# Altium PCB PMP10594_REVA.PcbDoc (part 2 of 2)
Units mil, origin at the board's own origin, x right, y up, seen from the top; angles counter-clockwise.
Board outline 4300 x 2600 mil, 4 copper layers (Top Layer, Signal Layer 1, Signal Layer 2, Bottom Layer), stack 61.2 mil thick; 149 components, 76 nets, 349 pads, 143 vias.
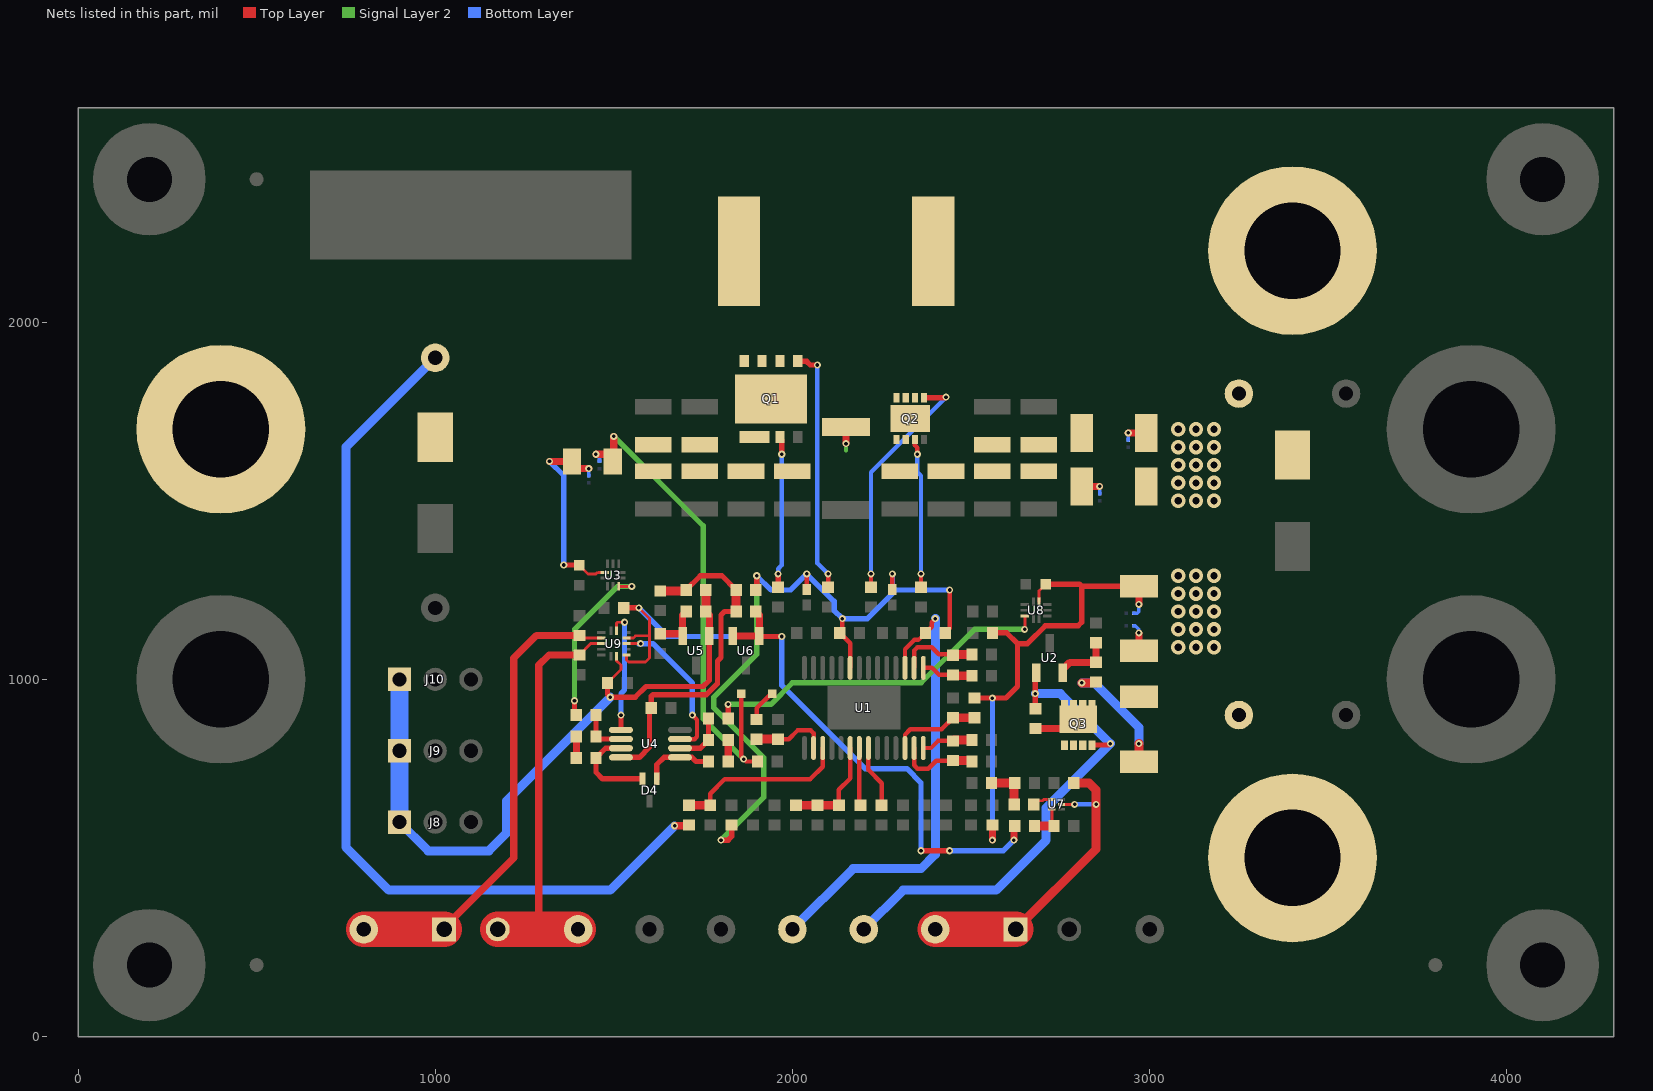
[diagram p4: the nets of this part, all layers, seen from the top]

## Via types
v1: diameter 20, hole 10, Top Layer to Bottom Layer, 105 vias
v2: diameter 40, hole 20, Top Layer to Bottom Layer, 38 vias

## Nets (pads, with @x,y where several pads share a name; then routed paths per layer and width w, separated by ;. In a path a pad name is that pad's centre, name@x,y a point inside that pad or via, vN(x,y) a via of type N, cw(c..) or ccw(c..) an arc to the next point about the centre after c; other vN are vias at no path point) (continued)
NetC15_1: C15.1 R15.1 U1.16 | length 220.9
  Top Layer w12.5: U1.16@2340.75,1032.2 2340.75,1080.75 2350,1090 2390,1090 2410,1070 2447.56,1070 C15.1@2450,1067.56
  Top Layer w25: C15.1@2452.44,1070 R15.1@2502.44,1070
NetC15_2: C15.2 R16.1 U1.15 | length 145.3
  Top Layer w12.5: U1.15@2366.34,1032.2 2390.55,1032.2 2410.31,1012.44 C15.2@2450,1012.44
  Top Layer w25: C15.2@2450,1012.44 2452.44,1010 R16.1@2502.44,1010
NetC16_1: C16.1 R17.2 | length 60
  Top Layer w20: R17.2@1395.04,780 C16.1@1395.04,840
NetC16_2: C16.2 R23.1 U4.6 | length 132.7
  Top Layer w15: R23.1@1450.16,900 C16.2@1450.16,840 1457.36,832.8 U4.6@1519.92,832.8
NetC18_1: C18.1 R18.2 U1.13 | length 220.9
  Top Layer w12.5: U1.13@2340.75,807.8 2340.75,759.25 2350,750 2380,750 2402.44,772.44 C18.1@2450,772.44
  Top Layer w25: C18.1@2450,772.44 R18.2@2500,772.44
NetC18_2: C18.2 R22.2 U1.14 | length 145.3
  Top Layer w12.5: U1.14@2366.34,807.8 2387.8,807.8 2407.56,827.56 C18.2@2450,827.56
  Top Layer w25: C18.2@2450,827.56 2452.44,830 R22.2@2502.44,830
NetC20_1: C20.1 R28.2 | length 60
  Top Layer w20: R28.2@1820.16,770 C20.1@1820.16,830
NetC20_2: C20.2 R33.1 U4.2 | length 149.2
  Top Layer w15: U4.2@1685.28,807.2 1742.24,807.2 C20.2@1765.04,830 R33.1@1765.04,890
NetC26_1: C26.1 R26.1 U7.6 | length 103.5
  Top Layer w7.87: C26.1@2726.48,595.83 U7.6@2726.48,636.22
  Top Layer w8: C26.1@2726.48,595.83 C26.1@2732.31,590
  Top Layer w25: R26.1@2677.43,590 C26.1@2732.31,590
NetD1_1: D1.1 R4.2 | length 92
  Top Layer w12.5: R4.2@1900,887.56 1900,919.5 1940.5,960 D1.1@1943.31,960
NetD4_1: D4.1 R28.1 U4.1 | length 198.1
  Top Layer w15: D4.1@1619.68,721.5 1619.68,760.79 1640.51,781.61 U4.1@1685.28,781.61 1718.39,781.61 1730,770 R28.1@1765.04,770
NetD4_2: D4.2 R17.1 U4.7 | length 258.9
  Top Layer w15: U4.7@1519.92,807.2 1477.36,807.2 R17.1@1450.16,780 1450.16,739.84 1468.5,721.5 D4.2@1580.31,721.5
NetL1_1: L1.1 Q1.6 Q1.7 Q1.8
NetL1_2: L1.2 Q2.6 Q2.7 Q2.8
NetNT5_1: NT5.1 Q1.9 Q2.9 RS4.2 | length 66.1
  Top Layer w20: v1(2150,1660) RS4.2@2150,1706.14
  Signal Layer 2 w10: NT5.1@2150,1640 v1(2150,1660)
NetNT8_2: NT8.2 Q3.5 Q3.6 Q3.7 Q3.8 Q3.9 R7.1 R9.1 RS5.2 | length 174.1
  Top Layer w20: R9.1@2680,862.44 Q3.9@2774.37,862.44 ; RS5.2@2970,1079.45 v1(2970,1130)
  Bottom Layer w10: NT8.2@2955,1150 2960,1150 2970,1140 v1(2970,1130)
NetQ1_3: Q1.3 RH1.2 | length 415.5
  Top Layer w15: RH1.2@1960,1257.56 v1(1960,1295) ; v1(1970,1630) Q1.3@1970,1668.9
  Bottom Layer w12.5: v1(1960,1295) 1960,1310 1970,1320 v1(1970,1630)
NetQ1_5: Q1.5 RL1.2 | length 694.5
  Top Layer w12.5: Q1.5@2015,1891.1 Q1.5@2016.1,1890 ; RL1.2@2100,1257.56 v1(2100,1295)
  Top Layer w15: Q1.5@2016.1,1890 2040,1890 2050,1880 v1(2070,1880)
  Bottom Layer w12.5: v1(2070,1880) 2070,1325 v1(2100,1295)
NetQ2_3: Q2.3 RH2.1 | length 421.3
  Top Layer w12.5: Q2.3@2342.8,1671.73 2342.8,1655.89 2350,1648.69 v1(2350,1630) ; RH2.1@2360,1257.56 v1(2360,1295)
  Bottom Layer w12.5: v1(2350,1630) 2350,1580 2360,1570 v1(2360,1295)
NetQ2_5: Q2.5 RL2.1 | length 681.8
  Top Layer w12.5: RL2.1@2220,1257.56 v1(2220,1295)
  Top Layer w15: Q2.5@2368.39,1788.27 2428.27,1788.27 v1(2430,1790)
  Bottom Layer w12.5: v1(2220,1295) 2220,1580 v1(2430,1790)
NetQ3_4: Q3.4 R9.2 TP8.1 U2.1 | length 1381.5
  Top Layer w15: R9.2@2680,917.56 v1(2680,960) 2680,1016.06 U2.1@2682.6,1018.66 ; Q3.4@2838.39,816.02 2886.02,816.02 v1(2890,820)
  Bottom Layer w25: TP8.1@2200,300 2310,410 2570,410 2710,550 2710,640 v1(2890,820) 2750,960 v1(2680,960)
NetR8_1: R8.1 R14.2 U2.2 | length 165.1
  Top Layer w20: U2.2@2757.4,1018.66 2757.4,1028.35 2776.61,1047.56 R8.1@2850,1047.56 R14.2@2850,1102.44
NetR23_2: R23.2 U3.10 | length 488.1
  Top Layer w7.85: U3.10@1513.67,1260.06 1549.94,1260.06 v1(1550,1260)
  Top Layer w15: v1(1390,940) 1390,905.04 R23.2@1395.04,900
  Signal Layer 2 w15: v1(1390,940) 1390,1140 1510,1260 v1(1550,1260)
NetR24_1: R24.1 R25.2 U5.2 | length 137.9
  Top Layer w20: R25.2@1630,1127.56 1686.38,1127.56 U5.2@1692.6,1121.34 1692.6,1180.16 R24.1@1702.44,1190
NetR33_2: R33.2 U8.10 | length 994.9
  Top Layer w7.87: v1@2650.98,1140.98 U8.10@2650.98,1177.64
  Top Layer w8.75: v1(2650,1140) v1@2650.98,1140.98
  Top Layer w15: R33.2@1820,890.16 v1(1820,930)
  Signal Layer 2 w15: v1(1820,930) 1939.5,930 2000,990.5 2360.5,990.5 2510,1140 v1(2650,1140)
PGOOD: R10.1 TP10.1 U1.17 | length 1326.9
  Top Layer w12.5: U1.17@2315.16,1032.2 2315.16,1084.58 2340.95,1110.37 2352.81,1110.37 R10.1@2372.44,1130 2390,1147.56 2390,1160 v1(2400,1170)
  Bottom Layer w25: TP10.1@2000,300 2170,470 2360,470 2400,510 v1(2400,1170)
REFB: C22.1 R29.1 R30.1 | length 123.5
  Top Layer w25: R30.1@2557.56,710 C22.1@2622.44,710 ; R29.1@2620.79,649.69 C22.1@2620.79,708.35
SCL: J11.2 R34.2 TP13.1 U9.10 | length 1164.4
  Top Layer w7.87: R34.2@1403.62,1068.18 1435.45,1100 U9.10@1464.57,1100
  Top Layer w20: 1290,300 1290,1040 1318.18,1068.18 R34.2@1403.62,1068.18
  Top Layer w100: J11.2@1175,300 TP13.1@1400,300
SDA: J11.1 R35.2 TP14.1 U9.9 | length 1339.5
  Top Layer w7.87: R35.2@1403.62,1123.06 1410.93,1115.75 U9.9@1464.57,1115.75
  Top Layer w20: J11.1@1025,300 1025,305 1220,500 1220,1060 1283.06,1123.06 R35.2@1403.62,1123.06
  Top Layer w100: TP14.1@800,300 J11.1@1025,300
SLOPE: C8.1 U1.7 | length 171.4
  Top Layer w12.5: C8.1@2187.2,640.35 U1.7@2187.2,807.8 ; C8.1@2187.2,650.35 C8.1@2190,647.56
SS: C9.1 U1.8 | length 175.6
  Top Layer w12.5: U1.8@2212.8,807.8 2212.8,746.68 2250,709.47 C9.1@2250,647.56
SYNC: C3.2 C10.2 R13.2 U1.6 | length 293.3
  Top Layer w12.5: C10.2@2130,647.56 2130,691.02 2161.61,722.64 U1.6@2161.61,807.8
  Top Layer w25: C3.2@2010,647.56 R13.2@2070,647.56 C10.2@2130,647.56
VBAT: J5.1 Q3.1 Q3.2 Q3.3 R7.2 R8.2 TP7.1 | length 348.7
  Top Layer w25: v1(2810,990) 2847.56,990 R8.2@2850,992.44 ; R7.2@2970,769.45 v1(2970,820)
  Bottom Layer w25: v1(2810,990) 2845.55,990 2970,865.55 v1(2970,820)
VCC: C5.1 D2.2 D3.2 R6.2 R10.2 R19.2 U1.23 | length 2090.4
  Top Layer w12.5: D2.2@2040,1251.65 v1(2040,1295) ; v1(2140,1170) 2140,1137.56 C5.1@2132.44,1130 2161.61,1100.83 U1.23@2161.61,1032.2 ; D3.2@2280,1251.65 v1@2280,1290 ; R10.2@2427.56,1130 2440,1142.44 v1(2440,1250)
  Top Layer w15: v1(1800,550) 1820,550 1830,560 R6.2@1830,592.44 ; R19.2@1897.56,1250 1900,1252.44 v1(1900,1290)
  Signal Layer 2 w15: v1(1800,550) 1920,670 1920,780.08 1780.08,920 1780.08,950.08 1900,1070 v1(1900,1290)
  Bottom Layer w15: v1(1900,1290) 1940,1250 1995,1250 v1(2040,1295) 2116.85,1218.15 2116.85,1193.15 v1(2140,1170) 2210,1170 2280,1240 2280,1250 ; v1(2280,1295) 2280,1250 ; v1(2440,1250) 2280,1250
VCCP: C19.1 C23.1 R19.1 R20.1 R21.1 U4.8 | length 982
  Top Layer w15: U4.8@1519.92,781.61 1571.61,781.61 1600,810 1600,914.65 C23.1@1605.04,919.69 1605.04,952.17 1610,957.13 1759.47,957.13 1790.28,987.93 1790.28,1051.38 1800,1061.1 1800,1180 1810,1190 R21.1@1842.44,1190 ; R20.1@1702.44,1250 1742.44,1290 1802.44,1290 R19.1@1842.44,1250
  Top Layer w25: C19.1@1630,1247.56 R20.1@1700,1247.56 ; R21.1@1842.44,1190 R19.1@1842.44,1250
VDD: C24.1 J8.1 J9.1 J10.1 R20.2 R24.2 U5.1 U9.14 | length 1946
  Top Layer w7.85: C24.1@1482.44,990 1520,1027.56 1520,1040 1507.87,1052.13 U9.14@1507.87,1064.57
  Top Layer w15: C24.1@1482.44,990 1482.44,957.56 v1(1490,950) 1560,950 1590,980 1750,980 1767.4,997.4 U5.1@1767.4,1121.34
  Top Layer w20: R24.2@1757.56,1190 1767.4,1180.16 U5.1@1767.4,1121.34
  Top Layer w25: R24.2@1757.56,1190 R20.2@1757.56,1250
  Bottom Layer w25: J8.1@900,600 980,520 1150,520 1200,570 1200,660 v1(1490,950)
  Bottom Layer w50: J8.1@900,600 J9.1@900,800 J10.1@900,1000
VIN: C17.1 Cin1.1 J1.1 NT1.1 R5.1 RS1.1 TP1.1 U3.6 | length 3130.2
  Top Layer w7.88: C17.1@1402.47,1320 1427.47,1295 1450,1295 1453.19,1298.19 1455.5,1298.19 1456.74,1299.43 U3.6@1474.3,1299.43
  Top Layer w15: v1(1360,1320) C17.1@1402.47,1320
  Top Layer w20: v1(1320,1610) RS1.1@1382.91,1610 1402.91,1590 v1(1430,1590) ; v1(1670,590) 1707.56,590 R5.1@1710,592.44
  Bottom Layer w10: NT1.1@1430,1570 v1(1430,1590)
  Bottom Layer w15: v1(1320,1610) 1360,1570 v1(1360,1320)
  Bottom Layer w25: TP1.1@1000,1900 750,1650 750,530 870,410 1490,410 v1(1670,590)
VIN_IC: C1.1 R4.1 U1.2 | length 214.1
  Top Layer w12.5: C1.1@1960,832.44 1989.68,832.44 2014.25,857.01 2051.5,857.01 2059.25,849.25 U1.2@2059.25,807.8
  Top Layer w25: R4.1@1900,832.44 C1.1@1960,832.44
VINC: Cin2.1 Cin3.1 Cin4.1 Cin5.1 Cin6.1 Cin7.1 D1.2 NT2.2 Q1.1 Q1.2 R3.2 RS1.2 | length 1428.4
  Top Layer w12.5: D1.2@1856.69,960 1856.69,783.31 v1(1863.35,776.65) 1870,770 R3.2@1902.44,770
  Top Layer w15: RS1.2@1477.09,1630 RS1.2@1497.09,1610
  Top Layer w20: v1(1450,1630) RS1.2@1477.09,1630 ; RS1.2@1500,1612.91 v1(1500,1680)
  Signal Layer 2 w15: v1(1500,1680) 1750,1430 1750,890 v1(1863.35,776.65)
  Bottom Layer w10: v1(1450,1630) 1460,1620 NT2.2@1460,1610
VINSNS: C6.2 R5.2 U1.3 | length 490.8
  Top Layer w12.5: C6.2@1770,647.56 1770,680 1810.75,720.75 2050,720.75 2084.84,755.59 U1.3@2084.84,807.8
  Top Layer w25: R5.2@1710,647.56 C6.2@1770,647.56
VOSNS: C14.1 R2.1 U1.12 | length 251.8
  Top Layer w12.5: U1.12@2315.16,807.8 2315.16,845.16 2330,860 2417.56,860 C14.1@2450,892.44
  Top Layer w25: C14.1@2450,892.44 R2.1@2510,892.44
VOUT: C21.1 Co1.1 J2.1 NT4.2 NT7.2 R1.2 R2.2 R27.2 RS2.2 RS3.2 RS5.1 TP2.1 U8.6 | length 1560.3
  Top Layer w7.85: U8.6@2690.35,1217.01 2690.35,1247.74 C21.1@2708.92,1266.31
  Top Layer w15: R2.2@2510,947.56 v1(2560,947.56) 2597.56,947.56 2630,980 2630,1100 ; R1.2@2560,1130 2600,1130 2630,1100 ; C21.1@2708.92,1266.31 2803.69,1266.31 2809.45,1260.55 ; RS5.1@2970,1260.55 2809.45,1260.55 ; 2630,1100 2658.07,1100 2708.07,1150 2800,1150 2810,1160 2810,1260 2809.45,1260.55
  Top Layer w20: v1(2560,550) R27.2@2560,592.44 ; v1(2940,1690) RS2.2@2990.55,1690 ; v1(2970,1210) RS5.1@2970,1260.55
  Bottom Layer w10: NT4.2@2940,1670 v1(2940,1690) ; NT7.2@2955,1185 2965.31,1185 2970,1189.69 v1(2970,1210)
  Bottom Layer w15: v1(2560,550) v1(2560,947.56)
  other v2: 3080,1090 3130,1090 3180,1090 3080,1140 3130,1140 3180,1140 3080,1190 3130,1190 3180,1190 3080,1240 3130,1240 3180,1240 3080,1290 3130,1290 3180,1290 3080,1500 3130,1500 3180,1500 3080,1550 3130,1550 3180,1550 3080,1600 3130,1600 3180,1600 3080,1650 3130,1650 3180,1650 3080,1700 3130,1700 3180,1700
VOUTC: Co2.1 Co3.1 Co4.1 Co5.1 Co6.1 Co7.1 NT3.2 Q2.1 Q2.2 RS2.1 RS3.1 | length 70.6
  Top Layer w20: RS3.1@2809.45,1540 v1(2860,1540)
  Bottom Layer w10: NT3.2@2860,1520 v1(2860,1540)
VPWM: J7.1 R31.2 TP11.1 U7.2 | length 875.7
  Top Layer w7.87: U7.2@2753.25,650 v1(2790,650)
  Top Layer w25: J7.1@2625,300 2850,525 v1(2850,650) 2850,690 2830,710 R31.2@2787.56,710
  Top Layer w100: TP11.1@2400,300 J7.1@2625,300
  Bottom Layer w12.5: v1(2790,650) v1(2850,650)
VREF: C25.2 R21.2 R26.2 U6.1 U6.2 U9.1 U9.4 | length 2135.9
  Top Layer w7.85: U9.1@1535.43,1068.5 1535.43,1054.57 1541.8,1048.2 1588.2,1048.2 1600,1060 1600,1120 ; U9.4@1535.43,1115.75 1554.92,1115.75 1560.97,1121.8 1598.2,1121.8 1600,1120 ; v1(1570,1200) 1600,1170 1600,1120
  Top Layer w15: C25.2@1527.56,1200 v1(1570,1200) ; U6.1@1907.4,1121.34 1908.74,1120 v1(1970,1120) ; v1(2360,520) v1(2440,520)
  Top Layer w20: U6.2@1832.6,1121.34 U6.1@1907.4,1121.34 1907.4,1180.16 R21.2@1897.56,1190 ; v1(2620,550) 2620,587.69 R26.2@2622.31,590
  Bottom Layer w15: v1(1570,1200) 1650,1120 v1(1970,1120) 1970,983.62 2203.62,750 2320.37,750 2360,710.37 v1(2360,520) ; v1(2440,520) 2590,520 v1(2620,550)
WA: U4.3 U9.3 | length 441.3
  Top Layer w7.88: U9.3@1535.43,1100 v1(1575,1100)
  Top Layer w12.5: U4.3@1685.28,832.8 1726.71,832.8 1732.86,838.95 1732.86,887.14 v1(1720,900)
  Bottom Layer w15: v1@1570,1100 1609.33,1100 1720,989.33 v1(1720,900)
WB: U4.5 U9.6 | length 351.2
  Top Layer w7.88: U9.6@1507.87,1135.43 1507.87,1157.87 1510,1160 v1(1530,1160)
  Top Layer w15: U4.5@1519.92,858.39 1519.92,899.92 v1(1520,900)
  Bottom Layer w15: v1(1520,900) 1520,960 1530,970 v1(1530,1160)
Y: R29.2 U7.4 | length 56.4
  Top Layer w7.87: 2703.78,663.78 U7.4@2726.48,663.78
  Top Layer w8: R29.2@2675.91,649.69 2686.22,660 2700,660 2703.78,663.78
pads on no net: FID1.1 FID2.1 FID3.1 H1.1 H2.1 H3.1 H4.1 Logo1.0 U3.1 U3.7 U7.1 U7.5 U8.1 U8.7

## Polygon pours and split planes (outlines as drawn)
GND on Signal Layer 2 "Signal Layer 2-GND" (solid, remove dead copper, pour order 50): 0,0 0,2600 4300,2600 4300,0 0,0
GND on Signal Layer 1 "Signal Layer 1-GND" (solid, remove dead copper, pour order 49): 0,0 0,2600 4300,2600 4300,0 0,0
VIN on Bottom Layer "Bottom Layer-VIN" (solid, remove dead copper, pour order 51): 30,2040 1090,2040 1090,1360 510,1360 30,1360
VBAT on Bottom Layer "Bottom Layer-VBAT" (solid, remove dead copper, pour order 53): 3100,1000 3460,1000 3460,760 3700,760 3700,30 3100,30
VOUT on Bottom Layer "Top Layer-VOUT" (solid, remove dead copper, pour order 52): 2970,1470 2970,2570 3700,2570 3700,2100 3700,1940 3646.67,1940 3540,1940 3460,1940 3460,1510 3460,1470
GND on Bottom Layer "Bottom Layer-GND" (solid, remove dead copper, pour order 54): 0,0 0,2600 4300,2600 4300,0 0,0
NetL1_2 on Top Layer "Top Layer-NETL1_2" (solid, remove dead copper, pour order 47): 2270,1780 2270,2570 2420,2570 2430,2570 2470,2570 2470,1820 2350,1820 2350,1780
NetL1_1 on Top Layer "Top Layer-NETL1_1" (solid, remove dead copper, pour order 46): 1775,1870 1775,2570 1980,2570 1980,1870
VBAT on Top Layer "Top Layer-VBAT" (solid, remove dead copper, pour order 45): 2720,830 2820,830 2820,790 2910,790 2910,830 3060,830 3060,1000 3400,1000 3460,1000 3460,760 3700,760 3700,30 3100,30 3100,400 2900,400 2900,740 2750,740 2750,770 2720,770
VOUT on Top Layer "Top Layer-VOUT" (solid, remove dead copper, pour order 44): 2920,1470 2920,2570 3700,2570 3700,2100 3700,1940 3646.67,1940 3540,1940 3460,1940 3460,1510 3460,1470
VOUTC on Top Layer "Top Layer-VOUTC" (solid, remove dead copper, pour order 43): 2230,1610 2230,1680 2330,1680 2330,1610 2430,1610 2430,1670 2470,1710 2760,1710 2760,1770 2880,1770 2890,1770 2890,1750 2890,1730 2890,1680 2890,1470 2880,1470 2760,1470 2760,1530 2230,1530
NetNT5_1 on Top Layer "Top Layer-RS" (solid, remove dead copper, pour order 42): 1810,1710 1810,1850 2250,1850 2250,1770 2440,1770 2440,1690 2220,1690 2220,1640 2060,1640 2060,1710
VINC on Top Layer "Top Layer-VINC" (solid, remove dead copper, pour order 41): 1460,1530 1460,1700 1940,1700 1940,1610 2060,1610 2060,1530
VIN on Top Layer "Top Layer-VIN" (solid, remove dead copper, pour order 40): 30,2040 1420,2040 1420,1550 700,1550 550,1400 510,1360 30,1360
GND on Top Layer "Top Layer-GND" (solid, remove dead copper, pour order 48): 0,0 0,2600 4300,2600 4300,0 0,0

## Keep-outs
Keep-Out Layer:
  lines w10: 6390,-5 ccw(c6390,0) 6395,0 ; -5,0 ccw(c0,0) 0,-5 ; -5,0 ccw(c0,0) 0,-5 ; -5,0 -5,2600 ; -5,2600 cw(c0,2600) 0,2605 ; -5,2600 cw(c0,2600) 0,2605 ; 0,-5 4300,-5 ccw(c4300,0) 4305,0 4305,2600 ; 0,2605 4300,2605 ; 4300,2605 cw(c4300,2600) 4305,2600 ; 4300,2605 cw(c4300,2600) 4305,2600 ; 1925,2000 1925,2395 2320,2395 2320,2000 1925,2000
  text ".Layer_Name" at 577,-858.49 h60

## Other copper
Top Layer:
  rectangle net VOUT: 3060,1050 3210,1190
  rectangle net NetNT8_2: 2720,850 2900,960
  rectangle net NetNT8_2: 2890,850 3040,1160
  rectangle net VOUT: 2890,1180 3210,1320
  text ".CopyrightYear" at 975,75 h60
  text "TI" at 1251,75 h60
  text "©" at 858,71.48 h105
  text ".Layer_Name" at 577,-858.49 h60
Bottom Layer:
  rectangle net VOUT: 3050,1050 3210,1730
  text ".VersionControl_RevNumber" at 4040,2660 h60
  text "SVN:" at 4300,2660 h60
  text "MADE IN U.S." at 1250,86.5 h60
  text "UL94V-0" at 2529.5,86.5 h60
  text ".Layer_Name" at 577,-858.49 h60

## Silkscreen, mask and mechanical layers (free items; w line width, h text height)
Top Overlay:
  text "LM5175 Buck/Boost Charger" at 565,2460 h60
  text ".PRJ_Number" at 3110,145 h60
  text ".PCB_Rev" at 3650,145 h60
  text ".Layer_Name" at 577,-858.49 h60
Bottom Overlay:
  text ".Layer_Name" at 577,-858.49 h60
Top Paste:
  text ".Layer_Name" at 577,-858.49 h60
Bottom Paste:
  text ".Layer_Name" at 577,-858.49 h60
Top Solder:
  text ".Layer_Name" at 577,-858.49 h60
  text ".Layer_Name" at 577,-858.49 h60
Bottom Solder:
  text ".Layer_Name" at 577,-858.49 h60
Drill Guide:
  text ".Layer_Name" at 577,-858.49 h60
M1 Board Outline:
  lines w10: 0,0 0,2600 4300,2600 4300,0 0,0 ; 1920,1995 2325,1995 2325,2400 1920,2400 1920,1995
  text ".Layer_Name" at 577,-858.49 h60
M2 Board Dimensions:
  rectangle: 0,-275 125,-150
  rectangle: 125,-400 500,-275
  lines w7: 0,-275 1000,-275 ; 125,-400 125,-150 ; 250,-400 250,-150 ; 500,-400 500,-150 ; 750,-400 750,-150 ; 0,-400 1000,-400 1000,-150 0,-150 0,-400
  text ".Layer_Name" at 577,-858.49 h60
M3 3D STEP Top:
  text ".Layer_Name" at 577,-858.49 h60
M4 3D STEP Bottom:
  text ".Layer_Name" at 577,-858.49 h60
M5 Assembly Top:
  lines w10: -292,-930.17 6308,-930.17 ; -292,-726.83 6310,-726.83 ; -292,-523.5 -292,-1133.5 3713,-1133.5 6310,-1133.5 6310,-523.5 -291.5,-523.5 -291.5,-1133.5 1284,-1133.5 ; 2173,-1133.5 2173,-523.5 ; 3440,-726.83 3440,-523.5 ; 4280,-726.83 4280,-523.5 ; 4902,-1140 4902,-937.17
  text "COMPONENTS MARKED 'DNP' SHOULD NOT BE POPULATED." at 1153.5,-318.5 h60
  text "ASSEMBLY VARIANT:" at 1153,-434 h60
  text ".VariantName" at 2189,-434 h60
  text "PCB VIEWED FROM TOP SIDE" at -228.5,-655.67 h60
  text "BOARD #:" at 2248,-655.67 h60
  text ".PRJ_Number" at 2793.5,-655.67 h60
  text "REV:" at 3638,-655.67 h60
  text ".PCB_Rev" at 3929.5,-655.67 h60
  text "SVN REV:" at 4476,-655.67 h60
  text ".VersionControl_RevNumber" at 4982,-655.67 h60
  text "PLOT NAME =" at -228.5,-1064.34 h60
  text ".plot_File_Name" at 577,-1064.34 h60
  text "GENERATED    :" at 2250,-1064.34 h60
  text ".Print_Date" at 3119.5,-1064.34 h60
  text ".Print_Time" at 3848.5,-1064.34 h60
  text "TEXAS INSTRUMENTS" at 5113,-1064.34 h60
M6 Assembly Bottom:
  lines w10: -292.5,-727.33 6309.5,-727.33 ; -290.5,-930.67 6309.5,-930.67 ; 1115.5,-1140.5 1115.5,-937.67 ; 1737.5,-727.33 1737.5,-524 ; 2577.5,-727.33 2577.5,-524 ; 3844.5,-1134 3844.5,-524 ; 4733.5,-1134 6309,-1134 6309,-524 -292.5,-524 -292.5,-1134 2304.5,-1134 6309.5,-1134 6309.5,-524
  text "COMPONENTS MARKED 'DNP' SHOULD NOT BE POPULATED." at 6102,-318 h60
  text ".VariantName" at 5058,-434 h60
  text "ASSEMBLY VARIANT:" at 6097,-434 h60
  text ".VersionControl_RevNumber" at 1035.5,-656.17 h60
  text "SVN REV:" at 1541.5,-656.17 h60
  text ".PCB_Rev" at 2088,-656.17 h60
  text "REV:" at 2379.5,-656.17 h60
  text ".PRJ_Number" at 3224,-656.17 h60
  text "BOARD #:" at 3769.5,-656.17 h60
  text "PCB VIEWED FROM BOTTOM SIDE" at 6246,-656.17 h60
  text "TEXAS INSTRUMENTS" at 904.5,-1064.84 h60
  text ".Print_Time" at 2169,-1064.84 h60
  text ".Print_Date" at 2898,-1064.84 h60
  text "GENERATED    :" at 3767.5,-1064.84 h60
  text ".plot_File_Name" at 5440.5,-1064.84 h60
  text "PLOT NAME =" at 6246,-1064.84 h60
M9 Title Sheet:
  drawing of 57 lines, arcs and shapes, not listed
  text "1" at 739.84,8036.5 h70
  text "2" at 3235.5,8036.5 h70
  text "3" at 5724.84,8036.5 h70
  text "4" at 8231.51,8036.5 h70
  text "5" at 10730.5,8036.5 h70
  text "6" at 13235.5,8036.5 h70
  text "A" at -416.5,6893.5 h70
  text "A" at 14383.5,6893.5 h70
  text "B" at -416.5,4513.5 h70
  text "B" at 14383.5,4513.5 h70
  text "C" at -416.5,2138.5 h70
  text "C" at 14383.5,2138.5 h70
  text "PROJECT TITLE:" at 11343.5,277.5 h45
  text ".PRJ_Title" at 11393.5,144.17 h70
  text "DESIGNED FOR:" at 11343.5,-23.5 h45
  text ".PRJ_Customer" at 11393.5,-163.5 h70
  text "D" at -416.5,-231.5 h70
  text "D" at 14383.5,-231.5 h70
  text "FILE NAME:" at 11343.5,-323.5 h45
  text ".PCB_File_Name_No_Path" at 11393.5,-443.5 h70
  text "Texas Instruments (TI) and/or its licensors do not warrant the accuracy or completeness of this specification" at 6374,-605.34 h45
  text "ENGINEER:" at 11343.5,-613.5 h45
  text "LAYOUT BY:" at 12848.5,-613.5 h45
  text "or any information contained therein. TI and/or its licensors do not warrant that this design will meet" at 6329.01,-718 h45
  text ".PRJ_Engineer" at 11393.5,-768.49 h70
  text ".PCB_Layout" at 12899,-768.49 h70
  text "the specifications, will be suitable for your application or fit for any particular purpose, or will operate in" at 6329.01,-830.67 h45
  text ".Layer_Name" at 577,-858.49 h60
  text "ALTIUM DESIGNER VERSION:" at 12848.5,-923.5 h45
  text "an implementation. TI and/or its licensors do not warrant that the design is production worthy. You should" at 6329.01,-943.33 h45
  text "completely validate and test your design implementation to confirm the system functionality for your application." at 6374,-1056 h45
  text ".print_Scale" at 11393.5,-1056.83 h70
  text ".Application_BuildNumber" at 12899,-1056.83 h70
  text "1" at 739.84,-1263.5 h70
  text "2" at 3235.5,-1263.5 h70
  text "3" at 5724.84,-1263.5 h70
  text "4" at 8231.51,-1263.5 h70
  text "5" at 10730.5,-1263.5 h70
  text "6" at 13235.5,-1263.5 h70
M10 Fab Notes:
  drawing of 185 lines, arcs and shapes, not listed
  text "DESIGN INFORMATION" at 12381.02,5910 h60
  text "MIN. TRACK WIDTH:" at 11736.46,5730 h60
  text "7.8" at 12775,5730 h60
  text "MIL" at 12987.46,5730 h60
  text "MIN. CLEARANCE:" at 11736.46,5598 h60
  text "0.2" at 12772.7,5598 h60
  text "mm" at 12987.46,5598 h60
  text "MIN. VIA PAD SIZE:" at 11736.46,5466 h60
  text "20" at 12802.71,5466 h60
  text "MIL" at 12987.46,5466 h60
  text "0.05mm (2MIL)" at 12431.46,5324.29 h60
  text "MINIMUM ANNULAR RING" at 11407.23,5320 h60
  text "EXTERNAL" at 13139.46,5320 h60
  text "PER" at 11607.23,5202 h60
  text "IPC-D-275 CLASS 2 LEVEL C" at 11827.23,5202 h60
  text "MIL, HOLES" at 13315.46,5089.71 h60
  text "+/-" at 12923,5089 h60
  text "+/-" at 13777,5089 h60
  text "REGISTRATION TOLERANCES:" at 11407.23,5084 h60
  text "METAL" at 12607,5084 h60
  text "5" at 13183.2,5084 h60
  text "3" at 14016.2,5084 h60
  text "MIL" at 14132.46,5084 h60
  text "CUTOUT INSIDE CORNER RADIUS:" at 9240,4920 h60
  text "MATERIAL:" at 11332.46,4874.54 h60
  text "0.040 [1.016mm] R.  (TYP.)" at 9430,4810 h60
  text "FR-4 High Tg" at 12318.9,4734.21 h60
  text "FR-408" at 11753.46,4725.64 h60
  text "OTHER" at 13241.46,4725.64 h60
  text "X" at 11600,4720 h60
  text "62 MIL (1.6mm) +/-10%" at 12073.56,4562.92 h60
  text "THICKNESS:" at 11407.23,4558.64 h60
  text "X" at 11945.4,4558.64 h60
  text "OTHER" at 13358.46,4558.64 h60
  text "TOLERANCE:" at 11407.23,4400.64 h60
  text "X" at 12246.53,4400.64 h60
  text "ANSI IPC-6012 TYPE 3 CLASS 2" at 12433.48,4400.64 h60
  text "OTHER +/-" at 12433.46,4244.64 h60
  text "BOW & TWIST:" at 11407.23,4087.64 h60
  text "X" at 12246.53,4087.64 h60
  text "ANSI IPC-6012 TYPE 3 CLASS 2" at 12433.48,4087.64 h60
  text "OTHER +/-" at 12433.46,3929.13 h60
  text "DRILLING:" at 11332.46,3790.64 h60
  text "REFERENCE:" at 11407.23,3673.64 h60
  text "X" at 12055.46,3673.64 h60
  text "AS SHOWN" at 12242.46,3673.64 h60
  text "X" at 12956.46,3673.64 h60
  text "NC_DRILL FILES" at 13093.46,3673.64 h60
  text "PTH MIN COPPER THICKNESS:" at 11407.23,3515.64 h60
  text "X" at 12757.46,3515.64 h60
  text "1MIL" at 12894.46,3515.64 h60
  text "OTHER" at 13391.46,3515.64 h60
  text "BOARD FINISH:" at 11332.46,3356.64 h60
  text "SILKSCREEN:" at 11487.68,3238.64 h60
  text "X" at 12436.46,3238.64 h60
  text "TOP" at 12562.46,3238.64 h60
  text "X" at 12946.46,3238.64 h60
  text "BOTTOM" at 13073.46,3238.64 h60
  text "SILKSCREEN COLOR:" at 11487.68,3071.64 h60
  text "X" at 12435.42,3071.64 h60
  text "WHITE" at 12562.46,3071.64 h60
  text "OTHER" at 13073.46,3071.64 h60
  text "SOLDER RESIST COLOR:" at 11487.68,2901.64 h60
  text "X" at 12055.42,2742.44 h60
  text "GREEN" at 12182.46,2742.44 h60
  text "BLUE" at 12773.46,2742.44 h60
  text "OTHER" at 13311.46,2742.44 h60
  text "IMMERSION GOLD (ENIG)" at 12393.46,2553.92 h60
  text "ENEPIG" at 13731,2550.64 h60
  text "SURFACE FINISH:" at 11332.46,2549.64 h60
  text "IMM. TIN/SILVER OR EQUIV" at 11662,2392.64 h60
  text "OTHER" at 13093.46,2392.64 h60
  text "X" at 11500,2385 h60
  text "ARRAY/PANEL:" at 11332.46,2213.64 h60
  text "X" at 12205,2210 h60
  text "CUT AND TRIM PER MECH LAYER 1" at 12393.46,2209.35 h60
  text "N.C. ROUTE" at 12393.46,2057.64 h60
  text "V. SCORE" at 13259.46,2057.64 h60
  text "CERTIFICATION:" at 11332.46,1920.64 h60
  text "MATERIALS AND WORKMANSHIP FOR ALL PCBS" at 12057.46,1920.64 h60
  text "TO MEET OR EXCEED THE REQUIREMENTS OF:" at 12057.46,1822.64 h60
  text "X" at 11683.96,1686.13 h60
  text "ANSI IPC-A-600F CLASS ->" at 11822.96,1686.13 h60
  text "X" at 13462.02,1686.13 h60
  text "2" at 13580.96,1686.14 h60
  text "1" at 13265.96,1684.64 h60
  text "3" at 13934.96,1684.64 h60
  text "X" at 11686.02,1526.64 h60
  text "UL 94V-0" at 11822.96,1526.64 h60
  text "X" at 12498.02,1526.64 h60
  text "RoHS" at 12634.96,1526.64 h60
  text "OTHER" at 13279.36,1526.64 h60
  text "PER ORDER" at 13676.42,1526.64 h60
  text "ADDITIONAL REQUIREMENTS:" at 11332.46,1385.64 h60
  text "MICROSECTION:" at 11407.23,1270.64 h60
  text "YES" at 12312.96,1270.64 h60
  text "REQUIRED" at 13174.46,1114.49 h60
  text "BARE BOARD ELEC. TEST:" at 11407.23,1111.64 h60
  text "NONE" at 12712.96,1111.64 h60
  text "PER ORDER" at 13766.46,1111.64 h60
  text "X" at 13640,1110 h60
  text "MANUFACTURER'S UL:" at 11407.23,954.64 h60
  text "RAIL" at 12572.96,950.35 h60
  text "METAL" at 13064.77,950.35 h60
  text "X" at 13440,950 h60
  text "SILK" at 13576.46,950.35 h60
  text ".Layer_Name" at 577,-858.49 h60
M11 Gerber Information:
  lines w10: -292,-930.17 6308,-930.17 ; -292,-726.83 6310,-726.83 ; -292,-523.5 -292,-1133.5 3713,-1133.5 6310,-1133.5 6310,-523.5 -291.5,-523.5 -291.5,-1133.5 1284,-1133.5 ; 2173,-1133.5 2173,-523.5 ; 3440,-726.83 3440,-523.5 ; 4280,-726.83 4280,-523.5 ; 4902,-1140 4902,-937.17
  text "ALL ARTWORK VIEWED FROM TOP SIDE" at -228.5,-655.67 h60
  text "BOARD #:" at 2248,-655.67 h60
  text ".PRJ_Number" at 2793.5,-655.67 h60
  text "REV:" at 3638,-655.67 h60
  text ".PCB_Rev" at 3929.5,-655.67 h60
  text "SVN REV:" at 4476,-655.67 h60
  text ".VersionControl_RevNumber" at 4982,-655.67 h60
  text "LAYER NAME =" at -228.5,-858.49 h60
  text "PLOT NAME =" at -228.5,-1064.34 h60
  text ".plot_File_Name" at 577,-1064.34 h60
  text "GENERATED    :" at 2250,-1064.34 h60
  text ".Print_Date" at 3119.5,-1064.34 h60
  text ".Print_Time" at 3848.5,-1064.34 h60
  text "TEXAS INSTRUMENTS" at 5113,-1064.34 h60
M12 Stackup:
  drawing of 295 lines, arcs and shapes, not listed
  text "Layer" at 9605.74,7700 h60
  text "Name" at 10015.66,7700 h60
  text "Material" at 10955.4,7700 h60
  text "Thickness" at 11815.16,7700 h60
  text "Constant" at 12465,7700 h60
  text "Board Layer Stack" at 13034.86,7700 h60
  text "1" at 9605.74,7580 h60
  text "Top Overlay" at 10015.66,7580 h60
  text "2" at 9605.74,7460 h60
  text "Top Solder" at 10015.66,7460 h60
  text "Solder Resist" at 10955.4,7460 h60
  text "0.40mil" at 11815.16,7460 h60
  text "3.5" at 12465,7460 h60
  text "3" at 9605.74,7340 h60
  text "Top Layer" at 10015.66,7340 h60
  text "Copper" at 10955.4,7340 h60
  text "2.80mil" at 11815.16,7340 h60
  text "4" at 9605.74,7220 h60
  text "Dielectric1" at 10015.66,7220 h60
  text "FR-4" at 10955.4,7220 h60
  text "20.00mil" at 11815.16,7220 h60
  text "4.8" at 12465,7220 h60
  text "5" at 9605.74,7100 h60
  text "Signal Layer 1" at 10015.66,7100 h60
  text "Copper" at 10955.4,7100 h60
  text "1.40mil" at 11815.16,7100 h60
  text "6" at 9605.74,6980 h60
  text "Dielectric 2" at 10015.66,6980 h60
  text "12.80mil" at 11815.16,6980 h60
  text "4.2" at 12465,6980 h60
  text "7" at 9605.74,6860 h60
  text "Signal Layer 2" at 10015.66,6860 h60
  text "Copper" at 10955.4,6860 h60
  text "1.40mil" at 11815.16,6860 h60
  text "8" at 9605.74,6740 h60
  text "Dielectric 3" at 10015.66,6740 h60
  text "FR-4" at 10955.4,6740 h60
  text "20.00mil" at 11815.16,6740 h60
  text "4.8" at 12465,6740 h60
  text "9" at 9605.74,6620 h60
  text "Bottom Layer" at 10015.66,6620 h60
  text "Copper" at 10955.4,6620 h60
  text "2.80mil" at 11815.16,6620 h60
  text "10" at 9605.74,6500 h60
  text "Bottom Solder" at 10015.66,6500 h60
  text "Solder Resist" at 10955.4,6500 h60
  text "0.40mil" at 11815.16,6500 h60
  text "3.5" at 12465,6500 h60
  text "11" at 9605.74,6380 h60
  text "Bottom Overlay" at 10015.66,6380 h60
  text ".Layer_Name" at 577,-858.49 h60
M13 Component Bodies Top:
  text ".Layer_Name" at 577,-858.49 h60
M14 Component Bodies Bottom:
  text ".Layer_Name" at 577,-858.49 h60
M15 Courtyards Top:
  text ".Layer_Name" at 577,-858.49 h60
M16 Courtyards Bottom:
  text ".Layer_Name" at 577,-858.49 h60
Drill Drawing:
  lines w1: 5547.89,2311.62 5560.35,2311.62 5560.35,2299.17 5585.26,2299.17 5585.26,2311.62 5597.71,2311.62 5597.71,2336.53 5585.26,2336.53 5585.26,2348.99 5560.35,2348.99 5560.35,2336.53 5547.89,2336.53 5547.89,2311.62 ; 5547.89,2448.63 5597.71,2448.63 5597.71,2498.45 5547.89,2498.45 5547.89,2448.63 ; 5547.89,2598.09 5547.89,2610.54 5560.35,2623 5547.89,2635.45 5547.89,2647.9 5560.35,2647.9 5572.8,2635.45 5585.26,2647.9 5597.71,2647.9 5597.71,2635.45 5585.26,2623 5597.71,2610.54 5597.71,2598.09 5585.26,2598.09 5572.8,2610.54 5560.35,2598.09 5547.89,2598.09 ; 5547.89,2747.54 5572.8,2760 5597.71,2747.54 5585.26,2772.45 5597.71,2797.36 5572.8,2784.91 5547.89,2797.36 5560.35,2772.45 5547.89,2747.54 ; 5547.89,2909.46 5560.35,2909.46 5572.8,2897 5585.26,2909.46 5597.71,2909.46 5585.26,2921.91 5597.71,2934.37 5585.26,2934.37 5572.8,2946.82 5560.35,2934.37 5547.89,2934.37 5560.35,2921.91 5547.89,2909.46 ; 5547.89,3096.28 5597.71,3096.28 5572.8,3046.46 5547.89,3096.28 ; 5547.89,3220.83 5572.8,3195.92 5597.71,3220.83 5572.8,3245.74 5547.89,3220.83
  lines w12: 5480,2254.33 7599.4,2254.33 ; 5480,3300.54 7599.4,3300.54 ; 5850.67,2104.87 5850.67,3450 ; 6207.78,2104.87 6207.78,3450 ; 6869.79,2104.87 6869.79,3450 ; 7154.14,2104.87 7154.14,3450 ; 5480,2104.87 7599.4,2104.87 7599.4,3450 5480,3450 5480,2104.87
  text "Symbol" at 5569.68,3345.38 h72
  text "Quantity" at 5895.51,3345.38 h72
  text "Finished Hole Size" at 6252.62,3345.38 h72
  text "Plated" at 6914.62,3345.38 h72
  text "Hole Type" at 7198.98,3345.38 h72
  text "105" at 5895.51,3195.92 h60
  text "10.00mil (0.254mm)" at 6252.62,3195.92 h60
  text "PTH" at 6914.62,3195.92 h60
  text "Round" at 7198.98,3195.92 h60
  text "38" at 5895.51,3046.46 h60
  text "20.00mil (0.508mm)" at 6252.62,3046.46 h60
  text "PTH" at 6914.62,3046.46 h60
  text "Round" at 7198.98,3046.46 h60
  text "9" at 5895.51,2897 h60
  text "39.37mil (1.000mm)" at 6252.62,2897 h60
  text "PTH" at 6914.62,2897 h60
  text "Round" at 7198.98,2897 h60
  text "14" at 5895.51,2747.54 h60
  text "40.00mil (1.016mm)" at 6252.62,2747.54 h60
  text "PTH" at 6914.62,2747.54 h60
  text "Round" at 7198.98,2747.54 h60
  text "4" at 5895.51,2598.09 h60
  text "43.31mil (1.100mm)" at 6252.62,2598.09 h60
  text "PTH" at 6914.62,2598.09 h60
  text "Round" at 7198.98,2598.09 h60
  text "4" at 5895.51,2448.63 h60
  text "125.98mil (3.200mm)" at 6252.62,2448.63 h60
  text "PTH" at 6914.62,2448.63 h60
  text "Round" at 7198.98,2448.63 h60
  text "6" at 5895.51,2299.17 h60
  text "270.00mil (6.858mm)" at 6252.62,2299.17 h60
  text "PTH" at 6914.62,2299.17 h60
  text "Round" at 7198.98,2299.17 h60
  text "180 Total" at 5895.51,2149.71 h60
  text ".Layer_Name" at 577,-858.49 h60

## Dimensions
0,-400 to 1000,-400 on M2 Board Dimensions
0,2600 to 0,0 on M2 Board Dimensions
4300,0 to 0,0 on M2 Board Dimensions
